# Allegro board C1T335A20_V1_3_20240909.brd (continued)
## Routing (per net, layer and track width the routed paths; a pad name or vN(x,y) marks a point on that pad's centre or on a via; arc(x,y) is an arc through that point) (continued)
TL_VBUS: length 24.7
  TOP w0.15: 50.69,55.33 50.51,55.33 ; 50.69,55.33 C49.1 ; 50.69,55.33 50.24,54.88 ; 50.51,55.33 50.34,55.33 49.89,54.88 ; 50.51,55.33 50.06,54.88
  TOP w0.2: C49.1 50.42,54.88 U8.32
  TOP w0.4: C49.1 51.67,56.13 53.25,56.13
  TOP w0.5: 53.25,56.13 67.12,56.13 v1(67.62,55.63)
  BOTTOM w0.5: J9.1 68.2,55.05 v1(67.62,55.63)
TL_VDCDCF: length 45.9
  TOP w0.2: 50.65,51.18 50.55,51.28 U8.23 ; 50.8,51.68 U8.24
  TOP w0.3: v1(72.8,53.33) 72.26,53.33 71.83,53.76 68.36,53.76 68.06,53.47 66.39,53.47 66.36,53.5 55.46,53.5 54.91,52.95
  TOP w0.35: 53.12,52.29 52.51,51.68 50.8,51.68 ; 50.65,51.18 52.92,51.18 53.13,51.4 C26.1 54.77,51.61 54.1,52.28
  TOP w0.5: 53.12,52.29 53.68,52.29 C24.1 54.1,52.28 54.77,52.95 54.91,52.95
  BOTTOM w0.5: v1(72.8,53.33) 74.12,52.01 74.12,42.85 74.62,42.35 J9.12
TL_VDD1P25: length 44.8
  TOP w0.2: U8.20 49.83,50.08 50.17,49.73 51,49.73 51.42,49.31
  TOP w0.35: v1(63.15,48.21) 54.53,48.21 C30.1 53.43,49.31 51.42,49.31
  BOTTOM w0.5: v1(63.15,48.21) 63.15,38.26 65.4,36.01 72.17,36.01 73.45,34.73 v1(74.2,34.73) J9.18 J9.16 J9.14
TL_VDD3_DCDC: length 38.6
  TOP w0.2: U8.17 48.77,48.38
  TOP w0.5: v1(54.48,31.34) 54.83,30.99 63.81,30.99 v1(63.84,31.01) ; 48.77,48.38 48.77,46.71 C23.1 49.98,45.98 50.33,45.63 50.33,44.46 50.83,43.96 v1(54.4,43.96)
  BOTTOM w0.5: J9.21 65.2,29.65 v1(63.84,31.01) ; v1(54.4,43.96) 54.48,43.88 v1(54.48,31.34)
TL_VDD_DMIC: length 94.3
  TOP w0.25: U6.2 32.15,22.12 U6.6 33.35,24.22 C42.1 35.62,25.26 36.08,24.81 36.08,18.66 38.49,16.24 51.83,16.24 53.16,14.91 v1(60.02,14.91)
  TOP w0.35: v1(79.58,23.36) 79.03,23.36 78.98,23.31 v1(65.97,23.31) 63.97,25.31 C41.1 63.42,24.18 U5.6
  BOTTOM w0.25: v1(65.97,23.31) 65.97,19.03 64.28,17.33 62.45,17.33 v1(60.02,14.91)
  BOTTOM w0.35: v1(79.58,23.36) 79.58,25.86 79.97,26.26 79.97,43.43 78.52,44.89 J9.10
TL_VDD_IR: length 34.6
  TOP w0.5: C37.2 68.25,68.33 R17.1 70.25,68.33 C36.2 70.95,67.93 71.97,66.91 71.97,66.53 R16.1 72.45,66.06 v1(73.33,66.06)
  BOTTOM w0.5: J9.8 79.53,47.43 80.03,47.93 80.03,63.33 78.9,64.45 73.83,64.45 73.33,64.95 v1(73.33,66.06)
TL_VDDCORE: length 31.6
  TOP w0.2: U8.15 47.38,45.58 47.58,45.38 C12.1 47.73,44.75 v1(47.73,42.73)
  TOP w0.3: v1(34.5,44.11) 34.52,44.08 v1(39.08,44.08)
  BOTTOM w0.3: v1(39.08,44.08) 45.68,44.08 46.98,42.79 47.67,42.79 v1(47.73,42.73)
  BOTTOM w0.35: J8.2 31.25,47.35 v1(34.5,44.11)
TL_VDDIO_AMS: length 79.6
  TOP w0.2: 46.98,56.89 46.98,55.88
  TOP w0.25: C50.1 51.33,58.93 49.01,58.93 46.98,56.89
  TOP w0.35: v1(82.75,34.18) 78.85,34.18 78.05,33.38 v1(74.17,33.38) ; v1(81.47,60.98) 81.3,61.16 71.35,61.16 71.08,60.88 67.97,60.88 67.33,61.53 53.92,61.53 C50.1
  BOTTOM w0.35: J9.19 72.98,32.19 v1(74.17,33.38) ; v1(82.75,34.18) 82.75,46.78 83.8,47.83 83.8,58.71 81.53,60.98 v1(81.47,60.98)
TL_VDDO3: length 90.9
  TOP w0.2: 47.38,56.66 U8.34
  TOP w0.25: C18.1 52.6,58.45 49.17,58.45 47.38,56.66
  TOP w0.35: C18.1 53.45,59.31 56.88,59.31 57.5,59.93 78.83,59.93 80.25,58.51 83.12,58.51 83.92,59.31 v1(87.42,59.31) v1(91.2,59.31)
  TOP w0.5: v1(78.33,32.19) 79.29,33.16 86.28,33.16 v1(87.42,34.31) ; v1(91.2,59.31) 91.5,59.01 R7.2
  BOTTOM w0.5: J9.24 J9.22 J9.20 v1(78.33,32.19) ; v1(87.42,59.31) v1(87.42,34.31)
TL_XC1: length 6.4
  TOP w0.15: Y1.3 45.05,60.99 C5.2 44.7,59.71 44.7,57.85 44.17,57.32 44.17,55.88
TL_XC2: length 9
  TOP w0.15: U8.41 44.58,57.26 45.05,57.73 45.05,58.96 C6.2 45.73,60.53 45.73,62.32 Y1.1
USB_VBUS: length 11.5
  TOP w0.5: R9.2 34.8,7.68 34.95,7.53 J2.A4B9 34.95,5.7 35.49,5.17 35.49,3.87 35.98,3.38 38.65,3.38 39.16,3.89 39.16,5.12 39.75,5.7 J2.B4A9
VCOM: length 45.5
  TOP w0.5: R30.2 R31.1 v1(88.88,40.41) ; v1(85.08,20.73) 85.12,20.68 v1(89.53,20.68)
  BOTTOM w0.5: v1(85.08,20.73) 74.28,20.73 72.97,22.03 J9.27 J9.29 ; v1(88.88,40.41) 89.53,39.76 v1(89.53,20.68)
VDW: length 37.9
  TOP w0.5: v1(88.88,39.41) R31.2 90.72,39.38 R32.1 ; v1(85.19,19.49) 88.86,19.49 v1(88.88,19.48)
  BOTTOM w0.5: v1(85.19,19.49) J9.30 J9.32 ; v1(88.88,39.41) v1(88.88,19.48)
VUP: length 39.7
  TOP w0.5: v1(88.9,41.81) 89.65,41.81 90.33,42.48 R30.1 90.7,44.56 R29.2 ; v1(90.17,22.01) 90.15,22.03 v1(85.08,22.03)
  BOTTOM w0.5: v1(88.9,41.81) 90.17,40.53 v1(90.17,22.01) ; J9.28 v1(85.08,22.03)
N20028206: length 3.1
  TOP w0.5: U7.1 88.72,43.62 R29.1 R33.1
N20230742: length 2
  TOP w0.5: R12.2 D1.A
N20265888: length 5
  TOP w0.5: J1.1 38.95,68.14 C45.1 L3.2
N20271178: length 7.4
  TOP w0.5: R16.2 71.53,63.46 70.45,64.53 D5.A
N20271193: length 1.6
  TOP w0.5: R17.2 D6.A
N20290987: length 4.9
  TOP w0.2: 50.5,49.23 50.1,49.23 49.65,49.68 U8.19
  TOP w0.35: 51.01,48.72 51.45,48.72 L2.1
  TOP w0.5: 50.5,49.23 51.55,48.18 51.55,48.01
N20305837: length 4.3
  TOP w0.25: J2.A5 36.1,8.91 R5.2
N20305839: length 1.9
  TOP w0.25: R10.2 39.1,8.16 J2.B5
N20310970: length 1.9
  TOP w0.5: C1.2 39.61,58.68 C2.1 38.94,59.31 L1.1
N20310976: length 1.8
  TOP w0.5: L1.2 38.93,60.41 C3.1 38.95,61.32 L3.1
N20338940: length 59.7
  TOP w0.15: v1(81.05,66.58) SW1.1 SW1.2 ; C53.1 43.38,57.81 v1(43.38,57.13) 42.98,56.73 42.6,56.73 42.17,56.31 42.17,55.88
  POWER w0.15: v1(43.38,57.13) 45.2,58.96 56.95,58.96 57.2,59.21 72.12,59.21 72.67,59.76 75.3,59.76 76.67,58.38 79.88,58.38 v1(81.5,60.01)
  BOTTOM w0.15: v1(81.5,60.01) 80.86,60.64 80.86,66.39 v1(81.05,66.58)
N20339485: length 2.7
  TOP w0.2: 44.98,55.88 44.98,56.78 45.69,57.49 45.69,57.79 C47.1
N20340397: length 6.1
  TOP w0.2: 49.72,48.86 49.3,49.28 U8.18
  TOP w0.35: 50.96,46.52 51.45,46.52 52.06,45.9
  TOP w0.5: 49.72,48.86 50.23,48.36 50.23,47.26 51.48,46.01 51.55,46.01
N20354870: length 4.6
  TOP w0.15: C51.1 62.23,10.23 61.88,9.88 J10.3
N20355410: length 2.3
  TOP w0.35: U4.4 C39.1 R18.2
N20355416: length 3.9
  TOP w0.15: U4.2 U4.3 55.77,20.98 C121.1 R34.2
N20355524: length 1.9
  TOP w0.15: C38.1 53.35,23.51 U4.1
N20367047: length 17.7
  TOP w0.15: J10.2 53.21,4.27 53.94,4.27 56.31,6.64 58.28,6.64 58.9,7.26 58.9,11.16 59.67,11.93 64.38,11.93 C52.1
N20394676: length 4.8
  TOP w0.15: R42.1 8.5,42.73 C120.2 C116.1 8,44.81 8.22,45.04 L17.2
N20394683: length 5
  TOP w0.15: L18.2 6.25,44.73 C117.2 6.75,43.48 C120.1 6.5,42.73 R43.1
N20394695: length 13.6
  TOP w0.15: R42.2 C119.1 8.5,34.98 9.75,33.73 9.75,31.73 8.65,30.63 J41.3
N20394699: length 4.8
  TOP w0.15: R43.2 C118.2 4.25,37.98 J41.2
N20394813: length 5.3
  TOP w0.15: L15.2 6.8,4.76 C115.1 C73.2 6.8,9.36 R40.1
N20394820: length 5.7
  TOP w0.15: L16.2 8.72,5.76 8.05,6.43 C69.2 7.8,8.11 C73.1 7.8,9.36 R41.1
N20394832: length 6.1
  TOP w0.15: R40.2 C76.1 6.3,14.28 7.15,15.13 J40.3
N20394836: length 19.1
  TOP w0.15: R41.2 C75.2 9.18,12.73 10,12.73 10.25,12.98 10.25,19.98 9,21.23 5,21.23 4.25,21.98 J40.2
N20397613: length 2
  TOP w0.5: R14.2 D2.A
N20397615: length 2
  TOP w0.5: R15.2 D3.A
N20397764: length 2
  TOP w0.5: R13.2 D4.A
N202309440: length 2.1
  TOP w0.15: R8.1 89.5,53.86 J3.2
N202309690: length 2.1
  TOP w0.15: R7.1 91.47,56.43 J3.4

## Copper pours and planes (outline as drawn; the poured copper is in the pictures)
GND on TOP: 1,0.3 0.51,0.51 0.3,1 0.3,67.43 1.1,69.38 3.05,70.18 22.25,70.18 37.36,70.18 37.36,70.17 37.36,65.7 38.68,64.38 39.19,64.38 40.49,65.68 40.49,70.18 89.55,70.18 91.49,69.37 92.3,67.43 92.3,4.19 90.95,2.84 70.26,2.84 67.72,0.3 22.25,0.3 ; 56 cut-outs
GND on BOTTOM: 1,0.3 0.51,0.51 0.3,1 0.3,67.43 1.1,69.38 3.05,70.18 89.55,70.18 91.5,69.38 92.3,67.43 92.3,4.19 90.95,2.84 70.26,2.84 67.72,0.3 ; 7 cut-outs
GND on GND: 1,0.3 0.51,0.51 0.3,1 0.3,67.43 1.1,69.38 3.05,70.18 89.55,70.18 91.5,69.38 92.3,67.43 92.3,4.19 90.95,2.84 70.26,2.84 67.72,0.3
GND on POWER: 1,0.3 0.51,0.51 0.3,1 0.3,67.43 1.1,69.38 3.05,70.18 89.55,70.18 91.5,69.38 92.3,67.43 92.3,4.19 90.95,2.84 70.26,2.84 67.72,0.3 ; 1 cut-out

Small or netless copper shapes (teardrops, artwork), in the pictures only: 241 on TOP, 74 on BOTTOM, 4 on POWER

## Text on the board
Ref Des/Silkscreen Bottom: GND | VBAT | VDD_CORE | 2024-09-09 | TL3218X-EVK64D | C1T335A20_V1_3 | VCOM | VFLASH | RFVDD1P25 | VDD3DCDC | AVDD3 | DVDD1P25 | VDDIOAMS | AVDD1P25 | TLVBUS | 3V3 | VUP | VDW | ADJ | VBUS | VDDF | VDDIR | TLVDDO3 | VDD1P25 | VDDDMIC
User.Comments: #4 | #3 | #1 | #2 | TOP | #5
Ref Des/Silkscreen Top: SWS | VBUS | TDI | NC | TCK | TMS | TDO | GND | 3V3 | IREX | LINE_P | LINE_N | SDM0 | SDM1 | PE3 | PA0 | PA2 | PA3 | PA4 | PD5 | PA1 | PE2 | PA5 | PE7 | PA6 | PE0 | PE1 | SDMN0 | SDMP0 | DMICCK2 | DMICCK1 | DMICDAT | PE4 | PE5 | PE6 | SDMP1 | SDMN1 | DM | DP | AUDIO-LINE-IN | PD0 | PB0 | PB1 | PB2 | PB3 | PB5 | PC7 | PB6 | PC5 | PC6 | PB7 | PB4 | PC1 | PC4 | PC0 | LEDW | LEDG | MIC_P | LEDR | IR | LEDB | PC2 | KEY3 | KEY4 | MIC_N | KEY1 | KEY2 | BIAS | PC3 | CHIP_RESET | 4-WIRE | 2-WIRE
DISPLAY_TOP: FIGURE | SIZE | 0.3 | 0.5 | 0.7 | 0.9 | 1.0 | DRILL CHART: TOP to BOTTOM | ALL UNITS ARE IN MILLIMETERS | PLATED | NON-PLATED | QTY | 1089 | 2 | 4 | 12 | 6
